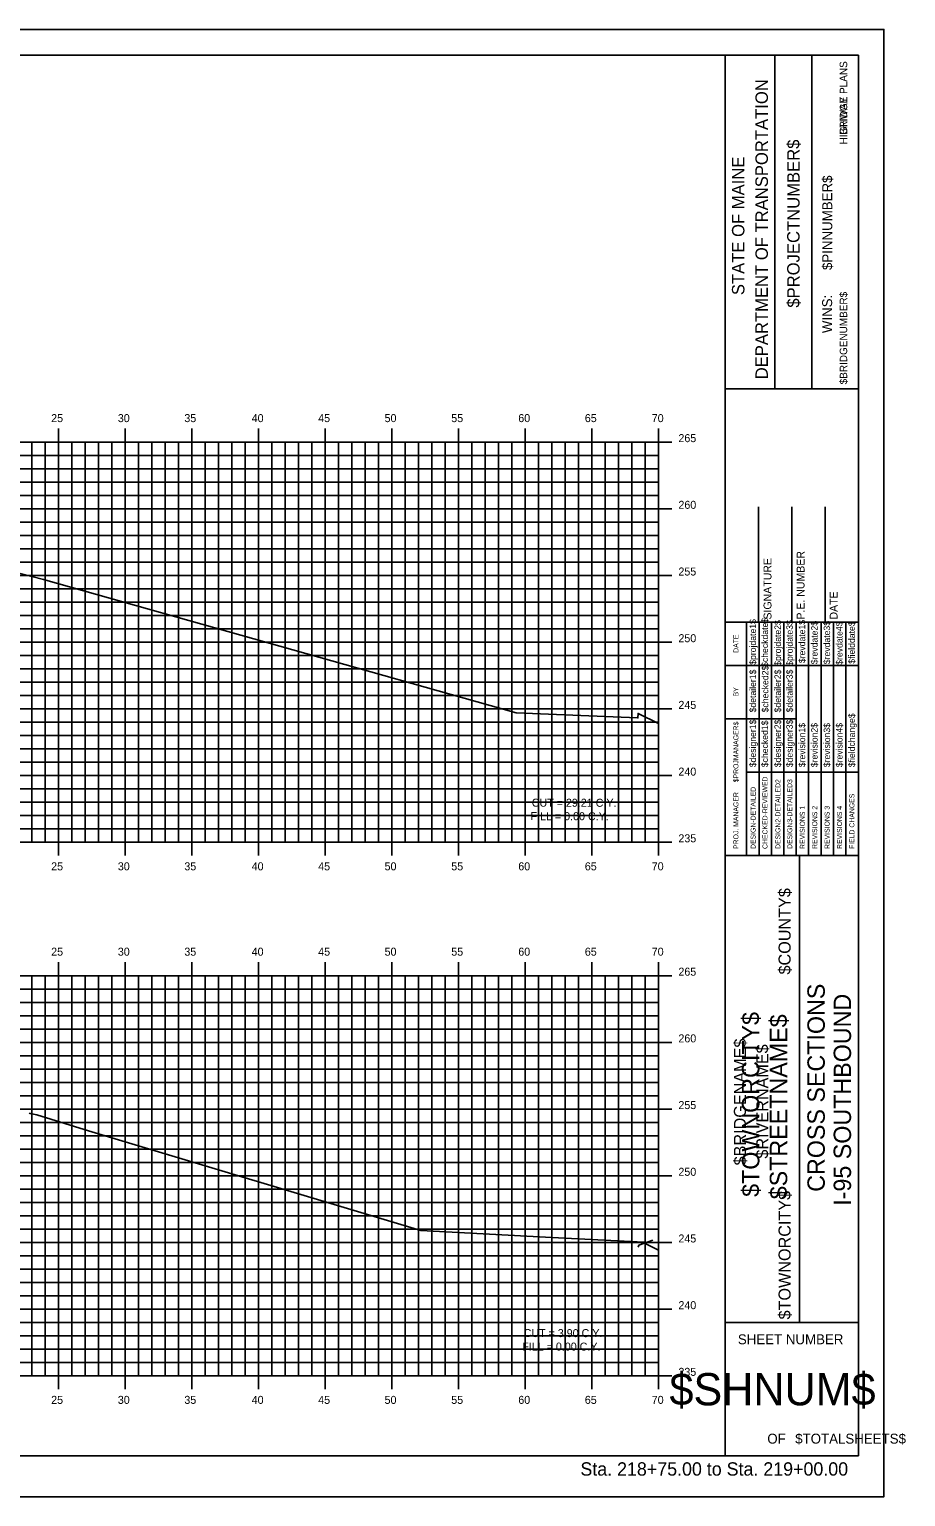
# Model space of a CAD drawing. Extents: x -22 to 1480, y -1511 to 8.
# Drawn here: x 83.8 to 149.5, y -184.5 to -74.5 of the extents above; entities that cross this region are included whole.
import ezdxf

# ---------------------------------------------------------------- set-up
doc = ezdxf.new("R2010")
doc.units = 0
for name, color, linetype in [('ANNOTATION', 7, 'Continuous'), ('BORDER', 7, 'Continuous'), ('BRIDGE_TITLE', 7, 'Continuous'), ('D_Utilities_UG_Water_Shutoff', 7, 'Continuous'), ('H_V ANNOTATION', 7, 'Continuous'), ('HIGHWAY_TITLE', 7, 'Continuous'), ('MAJOR', 7, 'Continuous'), ('MINOR', 7, 'Continuous'), ('PLOT BOUNDARY', 7, 'Continuous'), ('S_Roadway_Centerline', 7, 'Continuous')]:
    doc.layers.add(name, color=color, linetype=linetype)

msp = doc.modelspace()

# ---------------------------------------------------------------- linework, layer by layer
at = {"layer": 'BORDER'}
for p, q in [((145.94, -76.47), (-14.06, -76.47)), ((135.94, -181.46), (135.94, -76.46)), ((139.67, -101.47), (139.67, -76.47)), ((142.46, -101.47), (142.46, -76.47)), ((145.94, -181.46), (145.94, -76.46)), ((135.94, -101.47), (145.94, -101.47)), ((138.44, -118.96), (138.44, -110.32)), ((140.94, -118.96), (140.94, -110.32)), ((143.44, -118.96), (143.44, -110.32)), ((135.94, -118.96), (145.94, -118.96)), ((135.94, -136.46), (145.94, -136.46)), ((141.53, -171.46), (141.53, -136.46)), ((135.94, -171.46), (145.94, -171.46)), ((-14.06, -181.47), (145.94, -181.47))]:
    msp.add_line(p, q, dxfattribs=at)
for points in [[(137.55, -122.21), (137.55, -118.96)], [(137.56, -136.46), (137.56, -119.67)], [(138.49, -136.46), (138.49, -118.96)], [(139.42, -118.96), (139.42, -136.46)], [(140.35, -136.46), (140.35, -118.96)], [(141.28, -136.46), (141.28, -118.96)], [(142.21, -136.46), (142.21, -118.96)], [(143.15, -136.46), (143.15, -118.96)], [(144.08, -136.46), (144.08, -118.96)], [(145.01, -136.46), (145.01, -118.96)], [(135.94, -122.21), (145.94, -122.21)], [(135.94, -126.21), (137.56, -126.21)], [(137.55, -126.21), (141.28, -126.21)], [(137.55, -130.21), (145.94, -130.21)]]:
    msp.add_lwpolyline(points, dxfattribs=at)
at = {"layer": 'D_Utilities_UG_Water_Shutoff'}
msp.add_lwpolyline([(130.52, -165.3), (129.48, -165.68), (129.42, -165.81)], dxfattribs=at)
at = {"layer": 'MAJOR'}
for p, q in [((85.94, -104.46), (85.94, -105.47)), ((90.94, -104.46), (90.94, -105.47)), ((95.94, -104.46), (95.94, -105.47)), ((100.94, -104.46), (100.94, -105.47)), ((105.94, -104.46), (105.94, -105.47)), ((110.94, -104.46), (110.94, -105.47)), ((115.94, -104.46), (115.94, -105.47)), ((120.94, -104.46), (120.94, -105.47)), ((125.94, -104.46), (125.94, -105.47)), ((130.94, -104.46), (130.94, -105.47)), ((-9.06, -105.47), (130.94, -105.47)), ((-9.06, -105.47), (130.94, -105.47)), ((85.94, -135.47), (85.94, -105.47)), ((90.94, -135.47), (90.94, -105.47)), ((95.94, -135.47), (95.94, -105.47)), ((100.94, -135.47), (100.94, -105.47)), ((105.94, -135.47), (105.94, -105.47)), ((110.94, -135.47), (110.94, -105.47)), ((115.94, -135.47), (115.94, -105.47)), ((120.94, -135.47), (120.94, -105.47)), ((125.94, -135.47), (125.94, -105.47)), ((131.94, -105.47), (129.94, -105.47)), ((130.94, -135.47), (130.94, -105.47)), ((130.94, -135.47), (130.94, -105.47)), ((-9.06, -110.47), (130.94, -110.47)), ((131.94, -110.47), (129.94, -110.47)), ((-9.06, -115.47), (130.94, -115.47)), ((131.94, -115.47), (129.94, -115.47)), ((-9.06, -120.47), (130.94, -120.47)), ((131.94, -120.47), (129.94, -120.47)), ((-9.06, -125.47), (130.94, -125.47)), ((131.94, -125.47), (129.94, -125.47)), ((-9.06, -130.47), (130.94, -130.47)), ((131.94, -130.47), (129.94, -130.47)), ((-9.06, -135.47), (130.94, -135.47)), ((-9.06, -135.47), (130.94, -135.47)), ((85.94, -136.47), (85.94, -135.47)), ((90.94, -136.47), (90.94, -135.47)), ((95.94, -136.47), (95.94, -135.47)), ((100.94, -136.47), (100.94, -135.47)), ((105.94, -136.47), (105.94, -135.47)), ((110.94, -136.47), (110.94, -135.47)), ((115.94, -136.47), (115.94, -135.47)), ((120.94, -136.47), (120.94, -135.47)), ((125.94, -136.47), (125.94, -135.47)), ((131.94, -135.47), (129.94, -135.47)), ((130.94, -136.47), (130.94, -135.47)), ((85.94, -144.46), (85.94, -145.47)), ((90.94, -144.46), (90.94, -145.47)), ((95.94, -144.46), (95.94, -145.47)), ((100.94, -144.46), (100.94, -145.47)), ((105.94, -144.46), (105.94, -145.47)), ((110.94, -144.46), (110.94, -145.47)), ((115.94, -144.46), (115.94, -145.47)), ((120.94, -144.46), (120.94, -145.47)), ((125.94, -144.46), (125.94, -145.47)), ((130.94, -144.46), (130.94, -145.47)), ((-9.06, -145.47), (130.94, -145.47)), ((-9.06, -145.47), (130.94, -145.47)), ((85.94, -175.47), (85.94, -145.47)), ((90.94, -175.47), (90.94, -145.47)), ((95.94, -175.47), (95.94, -145.47)), ((100.94, -175.47), (100.94, -145.47)), ((105.94, -175.47), (105.94, -145.47)), ((110.94, -175.47), (110.94, -145.47)), ((115.94, -175.47), (115.94, -145.47)), ((120.94, -175.47), (120.94, -145.47)), ((125.94, -175.47), (125.94, -145.47)), ((131.94, -145.47), (129.94, -145.47)), ((130.94, -175.47), (130.94, -145.47)), ((130.94, -175.47), (130.94, -145.47)), ((-9.06, -150.47), (130.94, -150.47)), ((131.94, -150.47), (129.94, -150.47)), ((-9.06, -155.47), (130.94, -155.47)), ((131.94, -155.47), (129.94, -155.47)), ((-9.06, -160.47), (130.94, -160.47)), ((131.94, -160.47), (129.94, -160.47)), ((-9.06, -165.47), (130.94, -165.47)), ((131.94, -165.47), (129.94, -165.47)), ((-9.06, -170.47), (130.94, -170.47)), ((131.94, -170.47), (129.94, -170.47)), ((-9.06, -175.47), (130.94, -175.47)), ((-9.06, -175.47), (130.94, -175.47)), ((85.94, -176.47), (85.94, -175.47)), ((90.94, -176.47), (90.94, -175.47)), ((95.94, -176.47), (95.94, -175.47)), ((100.94, -176.47), (100.94, -175.47)), ((105.94, -176.47), (105.94, -175.47)), ((110.94, -176.47), (110.94, -175.47)), ((115.94, -176.47), (115.94, -175.47)), ((120.94, -176.47), (120.94, -175.47)), ((125.94, -176.47), (125.94, -175.47)), ((131.94, -175.47), (129.94, -175.47)), ((130.94, -176.47), (130.94, -175.47))]:
    msp.add_line(p, q, dxfattribs=at)
at = {"layer": 'MINOR'}
for p, q in [((83.94, -135.47), (83.94, -105.47)), ((84.94, -135.47), (84.94, -105.47)), ((86.94, -135.47), (86.94, -105.47)), ((87.94, -135.47), (87.94, -105.47)), ((88.94, -135.47), (88.94, -105.47)), ((89.94, -135.47), (89.94, -105.47)), ((91.94, -135.47), (91.94, -105.47)), ((92.94, -135.47), (92.94, -105.47)), ((93.94, -135.47), (93.94, -105.47)), ((94.94, -135.47), (94.94, -105.47)), ((96.94, -135.47), (96.94, -105.47)), ((97.94, -135.47), (97.94, -105.47)), ((98.94, -135.47), (98.94, -105.47)), ((99.94, -135.47), (99.94, -105.47)), ((101.94, -135.47), (101.94, -105.47)), ((102.94, -135.47), (102.94, -105.47)), ((103.94, -135.47), (103.94, -105.47)), ((104.94, -135.47), (104.94, -105.47)), ((106.94, -135.47), (106.94, -105.47)), ((107.94, -135.47), (107.94, -105.47)), ((108.94, -135.47), (108.94, -105.47)), ((109.94, -135.47), (109.94, -105.47)), ((111.94, -135.47), (111.94, -105.47)), ((112.94, -135.47), (112.94, -105.47)), ((113.94, -135.47), (113.94, -105.47)), ((114.94, -135.47), (114.94, -105.47)), ((116.94, -135.47), (116.94, -105.47)), ((117.94, -135.47), (117.94, -105.47)), ((118.94, -135.47), (118.94, -105.47)), ((119.94, -135.47), (119.94, -105.47)), ((121.94, -135.47), (121.94, -105.47)), ((122.94, -135.47), (122.94, -105.47)), ((123.94, -135.47), (123.94, -105.47)), ((124.94, -135.47), (124.94, -105.47)), ((126.94, -135.47), (126.94, -105.47)), ((127.94, -135.47), (127.94, -105.47)), ((128.94, -135.47), (128.94, -105.47)), ((129.94, -135.47), (129.94, -105.47)), ((-9.06, -106.47), (130.94, -106.47)), ((130.94, -106.47), (129.94, -106.47)), ((-9.06, -107.47), (130.94, -107.47)), ((130.94, -107.47), (129.94, -107.47)), ((-9.06, -108.47), (130.94, -108.47)), ((130.94, -108.47), (129.94, -108.47)), ((-9.06, -109.47), (130.94, -109.47)), ((130.94, -109.47), (129.94, -109.47)), ((-9.06, -111.47), (130.94, -111.47)), ((130.94, -111.47), (129.94, -111.47)), ((-9.06, -112.47), (130.94, -112.47)), ((130.94, -112.47), (129.94, -112.47)), ((-9.06, -113.47), (130.94, -113.47)), ((130.94, -113.47), (129.94, -113.47)), ((-9.06, -114.47), (130.94, -114.47)), ((130.94, -114.47), (129.94, -114.47)), ((-9.06, -116.47), (130.94, -116.47)), ((130.94, -116.47), (129.94, -116.47)), ((-9.06, -117.47), (130.94, -117.47)), ((130.94, -117.47), (129.94, -117.47)), ((-9.06, -118.47), (130.94, -118.47)), ((130.94, -118.47), (129.94, -118.47)), ((-9.06, -119.47), (130.94, -119.47)), ((130.94, -119.47), (129.94, -119.47)), ((-9.06, -121.47), (130.94, -121.47)), ((130.94, -121.47), (129.94, -121.47)), ((-9.06, -122.47), (130.94, -122.47)), ((130.94, -122.47), (129.94, -122.47)), ((-9.06, -123.47), (130.94, -123.47)), ((130.94, -123.47), (129.94, -123.47)), ((-9.06, -124.47), (130.94, -124.47)), ((130.94, -124.47), (129.94, -124.47)), ((-9.06, -126.47), (130.94, -126.47)), ((130.94, -126.47), (129.94, -126.47)), ((-9.06, -127.47), (130.94, -127.47)), ((130.94, -127.47), (129.94, -127.47)), ((-9.06, -128.47), (130.94, -128.47)), ((130.94, -128.47), (129.94, -128.47)), ((-9.06, -129.47), (130.94, -129.47)), ((130.94, -129.47), (129.94, -129.47)), ((-9.06, -131.47), (130.94, -131.47)), ((130.94, -131.47), (129.94, -131.47)), ((-9.06, -132.47), (130.94, -132.47)), ((130.94, -132.47), (129.94, -132.47)), ((-9.06, -133.47), (130.94, -133.47)), ((130.94, -133.47), (129.94, -133.47)), ((-9.06, -134.47), (130.94, -134.47)), ((130.94, -134.47), (129.94, -134.47)), ((83.94, -175.47), (83.94, -145.47)), ((84.94, -175.47), (84.94, -145.47)), ((86.94, -175.47), (86.94, -145.47)), ((87.94, -175.47), (87.94, -145.47)), ((88.94, -175.47), (88.94, -145.47)), ((89.94, -175.47), (89.94, -145.47)), ((91.94, -175.47), (91.94, -145.47)), ((92.94, -175.47), (92.94, -145.47)), ((93.94, -175.47), (93.94, -145.47)), ((94.94, -175.47), (94.94, -145.47)), ((96.94, -175.47), (96.94, -145.47)), ((97.94, -175.47), (97.94, -145.47)), ((98.94, -175.47), (98.94, -145.47)), ((99.94, -175.47), (99.94, -145.47)), ((101.94, -175.47), (101.94, -145.47)), ((102.94, -175.47), (102.94, -145.47)), ((103.94, -175.47), (103.94, -145.47)), ((104.94, -175.47), (104.94, -145.47)), ((106.94, -175.47), (106.94, -145.47)), ((107.94, -175.47), (107.94, -145.47)), ((108.94, -175.47), (108.94, -145.47)), ((109.94, -175.47), (109.94, -145.47)), ((111.94, -175.47), (111.94, -145.47)), ((112.94, -175.47), (112.94, -145.47)), ((113.94, -175.47), (113.94, -145.47)), ((114.94, -175.47), (114.94, -145.47)), ((116.94, -175.47), (116.94, -145.47)), ((117.94, -175.47), (117.94, -145.47)), ((118.94, -175.47), (118.94, -145.47)), ((119.94, -175.47), (119.94, -145.47)), ((121.94, -175.47), (121.94, -145.47)), ((122.94, -175.47), (122.94, -145.47)), ((123.94, -175.47), (123.94, -145.47)), ((124.94, -175.47), (124.94, -145.47)), ((126.94, -175.47), (126.94, -145.47)), ((127.94, -175.47), (127.94, -145.47)), ((128.94, -175.47), (128.94, -145.47)), ((129.94, -175.47), (129.94, -145.47)), ((-9.06, -146.47), (130.94, -146.47)), ((130.94, -146.47), (129.94, -146.47)), ((-9.06, -147.47), (130.94, -147.47)), ((-9.06, -148.47), (130.94, -148.47)), ((130.94, -147.47), (129.94, -147.47)), ((130.94, -148.47), (129.94, -148.47)), ((-9.06, -149.47), (130.94, -149.47)), ((130.94, -149.47), (129.94, -149.47)), ((-9.06, -151.47), (130.94, -151.47)), ((130.94, -151.47), (129.94, -151.47)), ((-9.06, -152.47), (130.94, -152.47)), ((130.94, -152.47), (129.94, -152.47)), ((-9.06, -153.47), (130.94, -153.47)), ((130.94, -153.47), (129.94, -153.47)), ((-9.06, -154.47), (130.94, -154.47)), ((130.94, -154.47), (129.94, -154.47)), ((-9.06, -156.47), (130.94, -156.47)), ((130.94, -156.47), (129.94, -156.47)), ((-9.06, -157.47), (130.94, -157.47)), ((130.94, -157.47), (129.94, -157.47)), ((-9.06, -158.47), (130.94, -158.47)), ((-9.06, -159.47), (130.94, -159.47)), ((130.94, -158.47), (129.94, -158.47)), ((130.94, -159.47), (129.94, -159.47)), ((-9.06, -161.47), (130.94, -161.47)), ((130.94, -161.47), (129.94, -161.47)), ((-9.06, -162.47), (130.94, -162.47)), ((130.94, -162.47), (129.94, -162.47)), ((-9.06, -163.47), (130.94, -163.47)), ((130.94, -163.47), (129.94, -163.47)), ((-9.06, -164.47), (130.94, -164.47)), ((130.94, -164.47), (129.94, -164.47)), ((-9.06, -166.47), (130.94, -166.47)), ((130.94, -166.47), (129.94, -166.47)), ((-9.06, -167.47), (130.94, -167.47)), ((130.94, -167.47), (129.94, -167.47)), ((-9.06, -168.47), (130.94, -168.47)), ((130.94, -168.47), (129.94, -168.47)), ((-9.06, -169.47), (130.94, -169.47)), ((130.94, -169.47), (129.94, -169.47)), ((-9.06, -171.47), (130.94, -171.47)), ((130.94, -171.47), (129.94, -171.47)), ((-9.06, -172.47), (130.94, -172.47)), ((130.94, -172.47), (129.94, -172.47)), ((-9.06, -173.47), (130.94, -173.47)), ((130.94, -173.47), (129.94, -173.47)), ((-9.06, -174.47), (130.94, -174.47)), ((130.94, -174.47), (129.94, -174.47))]:
    msp.add_line(p, q, dxfattribs=at)
at = {"layer": 'PLOT BOUNDARY'}
msp.add_lwpolyline([(-22.15, -184.53), (147.85, -184.53), (147.85, -74.53), (-22.15, -74.53)], close=True, dxfattribs=at)
at = {"layer": 'S_Roadway_Centerline'}
for points in [[(83.06, -115.32), (84.81, -115.77), (120.27, -125.76), (129.37, -126.13), (129.4, -126.14), (129.42, -125.81), (130.94, -126.57)], [(83.73, -155.78), (83.75, -155.78), (83.82, -155.8), (84.32, -155.9), (88.19, -157.1), (113.13, -164.58), (122.95, -165.09), (129.85, -165.45), (129.87, -165.45), (129.9, -165.53), (130.94, -166.05)]]:
    msp.add_lwpolyline(points, dxfattribs=at)

# ---------------------------------------------------------------- texts
at = {"layer": 'ANNOTATION'}
for s, p in [('CUT = 29.21 C.Y.', (121.44, -132.8)), ('FILL = 0.00 C.Y.', (121.35, -133.81)), ('CUT = 3.90 C.Y.', (120.83, -172.56)), ('FILL = 0.00 C.Y.', (120.73, -173.57))]:
    msp.add_text(s, height=0.6, rotation=359.9241, dxfattribs=at).set_placement(p)
at = {"layer": 'BORDER'}
for s, height, rotation, p in [('DEPARTMENT OF TRANSPORTATION', 0.9318, 90, (139.15, -100.76)), ('$PROJECTNUMBER$', 0.9318, 90, (141.53, -95.39)), ('STATE OF MAINE', 0.9318, 90, (137.39, -94.45)), ('$PINNUMBER$', 0.7453, 90, (143.98, -92.57)), ('WINS:', 0.745, 90, (143.97, -97.3)), ('SIGNATURE', 0.591, 90, (139.42, -118.77)), ('P.E. NUMBER', 0.5906, 90, (141.9, -118.77)), ('DATE', 0.591, 90, (144.38, -118.77)), ('$projdate1$', 0.4845, 90, (138.26, -122.16)), ('$checkdate$', 0.4845, 90, (139.16, -122.32)), ('$projdate2$', 0.4845, 90, (140.13, -122.24)), ('$projdate3$', 0.4845, 90, (141.02, -122.24)), ('$revdate1$', 0.485, 90, (141.95, -122.04)), ('$revdate2$', 0.485, 90, (142.88, -122.12)), ('$revdate3$', 0.485, 90, (143.82, -122.12)), ('$revdate4$', 0.485, 90, (144.75, -122.16)), ('$fielddate$', 0.4845, 90, (145.68, -122.08)), ('DATE', 0.371, 90, (136.94, -121.26)), ('$detailer1$', 0.4845, 90, (138.26, -125.73)), ('$checked2$', 0.485, 90, (139.19, -125.73)), ('$detailer2$', 0.4845, 90, (140.13, -125.73)), ('$detailer3$', 0.4845, 90, (141.02, -125.73)), ('BY', 0.371, 90, (136.94, -124.53)), ('$designer1$', 0.4845, 90, (138.26, -129.84)), ('$checked1$', 0.485, 90, (139.16, -129.84)), ('$designer2$', 0.4845, 90, (140.13, -129.84)), ('$designer3$', 0.4845, 90, (141.02, -129.84)), ('$fieldchange$', 0.4845, 90, (145.68, -129.84)), ('$PROJMANAGER$', 0.3727, 90, (136.94, -130.97)), ('$revision1$', 0.4845, 90, (141.95, -129.84)), ('$revision2$', 0.4845, 90, (142.88, -129.84)), ('$revision3$', 0.4845, 90, (143.82, -129.84)), ('$revision4$', 0.4845, 90, (144.75, -129.84)), ('CHECKED-REVIEWED', 0.3727, 90, (139.12, -135.97)), ('PROJ. MANAGER', 0.3727, 90, (136.94, -135.97)), ('DESIGN-DETAILED', 0.3727, 90, (138.23, -135.97)), ('DESIGN2-DETAILED2', 0.3727, 90, (140.09, -135.97)), ('DESIGN3-DETAILED3', 0.3727, 90, (140.98, -135.97)), ('FIELD CHANGES', 0.3727, 90, (145.64, -135.97)), ('REVISIONS 1', 0.3727, 90, (141.92, -135.97)), ('REVISIONS 2', 0.3727, 90, (142.85, -135.97)), ('REVISIONS 3', 0.3727, 90, (143.78, -135.97)), ('REVISIONS 4', 0.3727, 90, (144.71, -135.97)), ('CROSS SECTIONS', 1.3043, 90, (143.42, -161.67)), ('I-95 SOUTHBOUND', 1.3043, 90, (145.39, -162.72)), ('SHEET NUMBER', 0.7453, 360, (136.9, -173.1)), ('$SHNUM$', 2.419, 360, (131.77, -177.68)), ('OF', 0.745, 360, (139.11, -180.55)), ('$TOTALSHEETS$', 0.7453, 360, (141.2, -180.55))]:
    msp.add_text(s, height=height, rotation=rotation, dxfattribs=at).set_placement(p)
at = {"layer": 'BRIDGE_TITLE'}
for s, height, p in [('BRIDGE PLANS', 0.559, (145.1, -82.44)), ('$BRIDGENUMBER$', 0.559, (145.1, -101.14)), ('$COUNTY$', 0.907, (140.86, -145.38)), ('$BRIDGENAME$', 0.9072, (137.51, -159.69)), ('$RIVERNAME$', 0.9072, (139.18, -159.18)), ('$TOWNORCITY$', 0.9072, (140.86, -171.24))]:
    msp.add_text(s, height=height, rotation=90, dxfattribs=at).set_placement(p)
at = {"layer": 'H_V ANNOTATION'}
for s, height, p in [('25', 0.6, (85.39, -103.97)), ('30', 0.6, (90.39, -103.97)), ('35', 0.6, (95.38, -103.97)), ('40', 0.6, (100.43, -103.97)), ('45', 0.6, (105.42, -103.97)), ('50', 0.6, (110.4, -103.97)), ('55', 0.6, (115.4, -103.97)), ('60', 0.6, (120.43, -103.97)), ('65', 0.6, (125.42, -103.97)), ('70', 0.6, (130.44, -103.97)), ('265', 0.6, (132.44, -105.47)), ('260', 0.6, (132.44, -110.47)), ('255', 0.6, (132.44, -115.47)), ('250', 0.6, (132.44, -120.47)), ('245', 0.6, (132.44, -125.47)), ('240', 0.6, (132.44, -130.47)), ('235', 0.6, (132.44, -135.47)), ('25', 0.6, (85.39, -137.57)), ('30', 0.6, (90.39, -137.57)), ('35', 0.6, (95.38, -137.57)), ('40', 0.6, (100.43, -137.57)), ('45', 0.6, (105.42, -137.57)), ('50', 0.6, (110.4, -137.57)), ('55', 0.6, (115.4, -137.57)), ('60', 0.6, (120.43, -137.57)), ('65', 0.6, (125.42, -137.57)), ('70', 0.6, (130.44, -137.57)), ('25', 0.6, (85.39, -143.97)), ('30', 0.6, (90.39, -143.97)), ('35', 0.6, (95.38, -143.97)), ('40', 0.6, (100.43, -143.97)), ('45', 0.6, (105.42, -143.97)), ('50', 0.6, (110.4, -143.97)), ('55', 0.6, (115.4, -143.97)), ('60', 0.6, (120.43, -143.97)), ('65', 0.6, (125.42, -143.97)), ('70', 0.6, (130.44, -143.97)), ('265', 0.6, (132.44, -145.47)), ('260', 0.6, (132.44, -150.47)), ('255', 0.6, (132.44, -155.47)), ('250', 0.6, (132.44, -160.47)), ('245', 0.6, (132.44, -165.47)), ('240', 0.6, (132.44, -170.47)), ('235', 0.6, (132.44, -175.47)), ('25', 0.6, (85.39, -177.57)), ('30', 0.6, (90.39, -177.57)), ('35', 0.6, (95.38, -177.57)), ('40', 0.6, (100.43, -177.57)), ('45', 0.6, (105.42, -177.57)), ('50', 0.6, (110.4, -177.57)), ('55', 0.6, (115.4, -177.57)), ('60', 0.6, (120.43, -177.57)), ('65', 0.6, (125.42, -177.57)), ('70', 0.6, (130.44, -177.57)), ('Sta. 218+75.00 to Sta. 219+00.00', 1.0002, (125.09, -182.95))]:
    msp.add_text(s, height=height, dxfattribs=at).set_placement(p)
at = {"layer": 'HIGHWAY_TITLE'}
for s, height, p in [('HIGHWAY PLANS', 0.559, (145.1, -83.15)), ('$TOWNORCITY$', 1.3043, (138.51, -162.05)), ('$STREETNAME$', 1.3043, (140.6, -162.23))]:
    msp.add_text(s, height=height, rotation=90, dxfattribs=at).set_placement(p)

doc.saveas('drawing.dxf')
